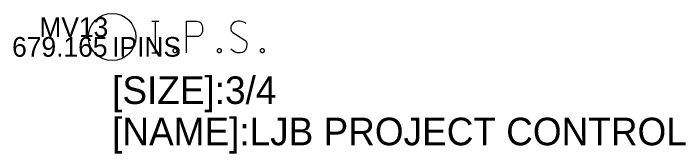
# Model space of a CAD drawing. Extents: x 1660019 to 1662995, y 619975 to 620342.
# Drawn here: x 1660019.38 to 1660053.44, y 620210.6 to 620217.72 of the extents above; entities that cross this region are included whole.
import ezdxf

# ---------------------------------------------------------------- set-up
doc = ezdxf.new("R2010")
doc.units = 0
for name, color, linetype in [('BR_X_Rail_Object', 7, 'Continuous'), ('RD_X_GR_Bar', 7, 'Continuous'), ('RD_X_Wall', 7, 'Continuous'), ('SV_P_Mon_Cells_Set_Text', 7, 'Continuous'), ('SV_X_Break_Lines', 7, 'Continuous')]:
    doc.layers.add(name, color=color, linetype=linetype)

msp = doc.modelspace()

# ---------------------------------------------------------------- linework, layer by layer
at = {"layer": 'SV_X_Break_Lines'}
for points in [[(1660026.398, 620217.323), (1660026.751, 620217.323)], [(1660026.574, 620215.723), (1660026.574, 620217.323)], [(1660028.14, 620215.723), (1660028.14, 620217.323), (1660028.669, 620217.323), (1660028.724, 620217.31), (1660028.801, 620217.285), (1660028.834, 620217.26), (1660028.867, 620217.234), (1660028.911, 620217.171), (1660028.944, 620217.108), (1660028.966, 620217.008), (1660028.966, 620216.856), (1660028.955, 620216.806), (1660028.933, 620216.73), (1660028.889, 620216.642), (1660028.845, 620216.605), (1660028.812, 620216.579), (1660028.757, 620216.554), (1660028.669, 620216.542), (1660028.14, 620216.542)], [(1660031.149, 620217.209), (1660031.127, 620217.234), (1660031.094, 620217.26), (1660030.995, 620217.297), (1660030.873, 620217.323), (1660030.785, 620217.323), (1660030.752, 620217.323), (1660030.609, 620217.285), (1660030.488, 620217.209), (1660030.41, 620217.108), (1660030.388, 620217.008), (1660030.388, 620216.932), (1660030.41, 620216.831), (1660030.499, 620216.743), (1660031.105, 620216.365), (1660031.16, 620216.315), (1660031.182, 620216.264), (1660031.204, 620216.189), (1660031.204, 620216.113), (1660031.193, 620216.038), (1660031.182, 620215.987), (1660031.16, 620215.924), (1660031.138, 620215.874), (1660031.116, 620215.836), (1660031.083, 620215.798), (1660031.05, 620215.773), (1660031.006, 620215.748), (1660030.973, 620215.735), (1660030.873, 620215.723), (1660030.719, 620215.723), (1660030.62, 620215.748), (1660030.476, 620215.836), (1660030.388, 620215.912)], [(1660026.398, 620215.723), (1660026.751, 620215.723)], [(1660027.533, 620215.937), (1660027.588, 620215.937), (1660027.622, 620215.912), (1660027.655, 620215.861), (1660027.655, 620215.798), (1660027.622, 620215.748), (1660027.588, 620215.723), (1660027.533, 620215.723), (1660027.5, 620215.748), (1660027.467, 620215.798), (1660027.467, 620215.861), (1660027.5, 620215.912), (1660027.533, 620215.937)], [(1660029.782, 620215.937), (1660029.837, 620215.937), (1660029.87, 620215.912), (1660029.903, 620215.861), (1660029.903, 620215.798), (1660029.87, 620215.748), (1660029.837, 620215.723), (1660029.782, 620215.723), (1660029.749, 620215.748), (1660029.716, 620215.798), (1660029.716, 620215.861), (1660029.749, 620215.912), (1660029.782, 620215.937)], [(1660031.965, 620215.937), (1660032.02, 620215.937), (1660032.053, 620215.912), (1660032.086, 620215.861), (1660032.086, 620215.798), (1660032.053, 620215.748), (1660032.02, 620215.723), (1660031.965, 620215.723), (1660031.931, 620215.748), (1660031.899, 620215.798), (1660031.899, 620215.861), (1660031.931, 620215.912), (1660031.965, 620215.937)]]:
    msp.add_lwpolyline(points, dxfattribs=at)
msp.add_circle((1660024.379, 620216.521), 1.2, dxfattribs=at)

# ---------------------------------------------------------------- texts
at = {"layer": 'BR_X_Rail_Object'}
msp.add_text('IPINS', height=1, dxfattribs=at).set_placement((1660024.379, 620215.521))
at = {"layer": 'RD_X_GR_Bar'}
msp.add_text('679.165', height=1, dxfattribs=at).set_placement((1660019.309, 620215.521))
at = {"layer": 'RD_X_Wall'}
msp.add_text('MV13', height=1, dxfattribs=at).set_placement((1660020.689, 620216.521))
at = {"layer": 'SV_P_Mon_Cells_Set_Text'}
for s, p in [('[SIZE]:3/4', (1660024.379, 620213.121)), ('[NAME]:LJB PROJECT CONTROL', (1660024.379, 620211.021))]:
    msp.add_text(s, height=1.4, dxfattribs=at).set_placement(p)

doc.saveas('drawing.dxf')
